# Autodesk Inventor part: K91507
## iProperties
Author: Administrator
Shininess: 20.0
PropertySet Name: _Private Model Information
Length Units: 11272
Angle Units: 11286
Time Units: 11279
Mass Units: 11290
Length Display Precision: 3
Angle Display Precision: 2
Compacted: False
Created: 2001-03
Part Number: K91507
Document SubType Name: Modeling
Designer: Administrator
Description: Timken Tongued Washer, 1.396 in ID x 2.173 in
Material: Steel, High Strength Low Alloy
Control State: 0
Master: False
Checked Out: False
PropertySet Name: Design Tracking Control
Density: 7.84
Volumn: 4.480880189906072
Area: 37.34926219948888
PropertySet Name: Model Information
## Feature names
1. Extrusion1
